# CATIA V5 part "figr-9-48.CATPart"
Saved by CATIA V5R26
Part number: Part1
Bounding box of the stored display mesh (mm): x -53.419 to 50, y -50 to 50, z -57.709 to 133.109
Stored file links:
  D:\_Deepak\CATIA\CATIA V5-6R2016_Deepak\Resources\Part files\Partfiles\c09_catia_v5_6r2016_prt\figr-9-48.CATPart
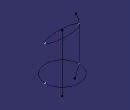
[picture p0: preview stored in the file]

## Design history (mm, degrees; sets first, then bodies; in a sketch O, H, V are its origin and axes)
Body1 (main body)
  Plane1: type Offset, RefPlane xy-plane, Offset 103
  Sketch1 on Plane1, origin (0, 0, 103), H (1, 0, 0), V (0, 1, 0)
    ellipse A1 centre (0, 0) semi-axes 50, 13.2069 rotation 0
    point P1 (50, 0)
    "Radius" A1 = 50
    coincidence: P1 H, A1 P1
  Extremum1: Reference Sketch1, Direction (1, 2, 3)
  Sketch2 on xy-plane, origin (0, 0, 0), H (1, 0, 0), V (0, 1, 0)
    circle A1 centre (0, 0) radius 50
    radius A1 = 50
  Extremum2: Reference Sketch2, Direction (1, 2, 3)
  Sketch3 on zx-plane, origin (0, 0, 0), H (-1, 0, 0), V (0, 0, 1)
    spline S1 through (37.7591, -31.0289) (41.8235, -21.251) (50, 0) (49.8084, 85.7657) (50, 103) (41.6255, 133.1089)
    reference projected line E1 (-50, 103) -> (50, 103) from Sketch1.A1
    point P1 (50, 0)
    point P2 (50, 103)
    distance V P1 = 50
    distance P2 V = 50
    coincidence: P1 H, P2 E1
  Sketch4 on zx-plane, origin (0, 0, 0), H (-1, 0, 0), V (0, 0, 1)
    line L1 (0, 111.062) -> (0, -57.7094)
    point P1 (0, 111.062)
    coincidence: P1 V
    vertical: L1 V
  Loft1: solid, Sections (Sketch1; Sketch2), Spine Sketch4, Guides Sketch3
